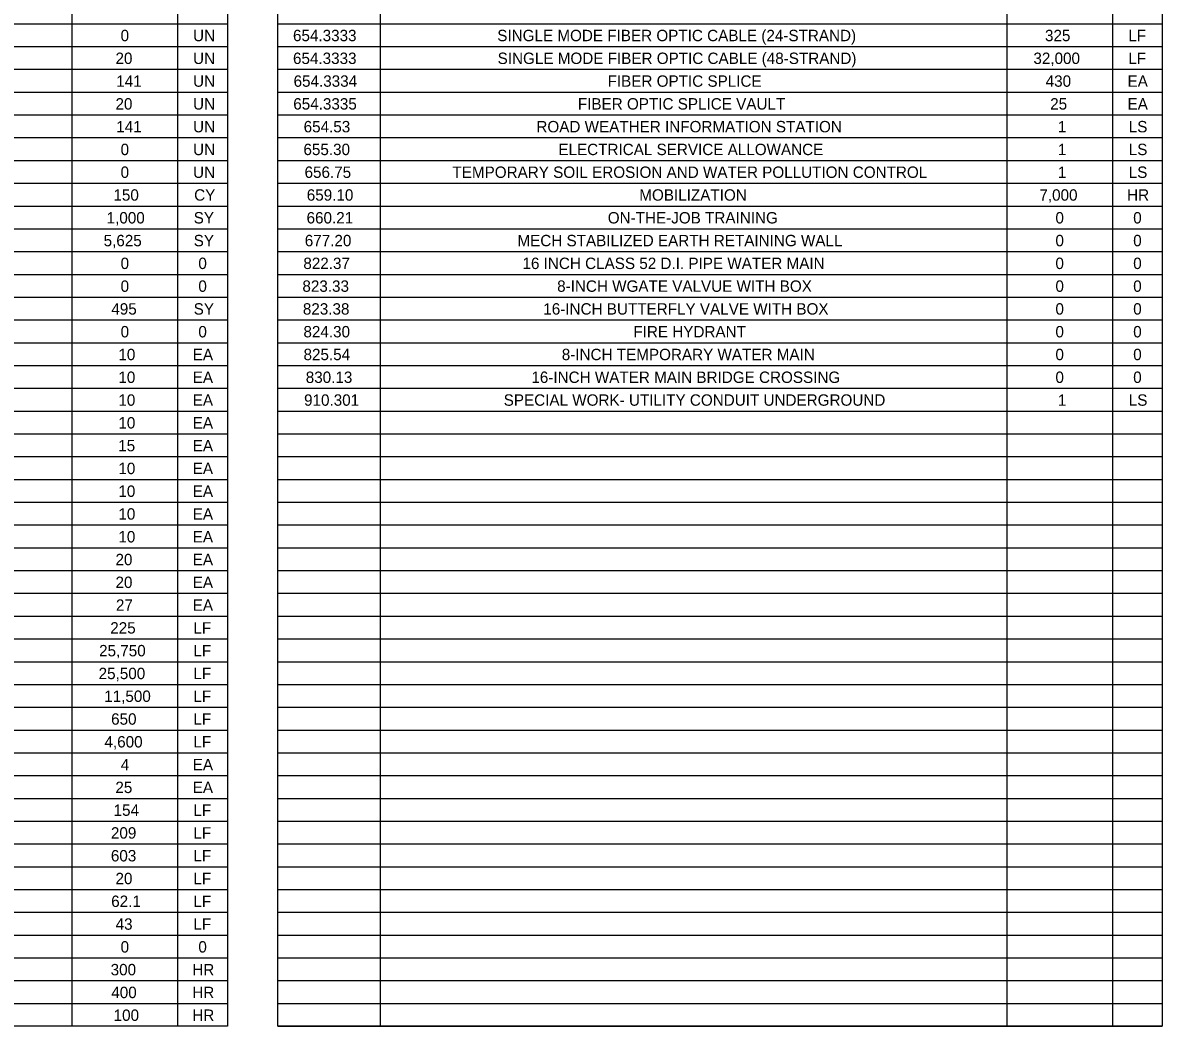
# Model space of a CAD drawing. Extents: x -18.7 to 5.6, y -2.7 to 4.
# Drawn here: x 4.632 to 5.617, y 0.019 to 0.886 of the extents above; entities that cross this region are included whole.
import ezdxf

# ---------------------------------------------------------------- set-up
doc = ezdxf.new("R2010")
doc.units = 0
doc.layers.add('ANNOTATION', color=7, linetype='Continuous')
doc.layers.add('BORDER', color=7, linetype='Continuous')

msp = doc.modelspace()

# ---------------------------------------------------------------- linework, layer by layer
at = {"layer": 'BORDER'}
for p, q in [((4.67472, 1.73155), (4.67472, 0.01886)), ((4.76611, 1.73155), (4.76611, 0.01886)), ((4.94124, 1.73155), (4.94124, 0.01886)), ((5.48258, 1.73155), (5.48258, 0.01886)), ((5.57397, 1.73155), (5.57397, 0.01886)), ((3.9448, 0.88505), (4.8091, 0.88505)), ((4.85265, 0.88505), (5.61696, 0.88505)), ((3.9448, 0.86536), (4.8091, 0.86536)), ((4.85265, 0.86536), (5.61696, 0.86536)), ((3.9448, 0.84568), (4.8091, 0.84568)), ((4.85265, 0.84568), (5.61696, 0.84568)), ((3.9448, 0.82599), (4.8091, 0.82599)), ((4.85265, 0.82599), (5.61696, 0.82599)), ((3.9448, 0.8063), (4.8091, 0.8063)), ((4.85265, 0.8063), (5.61696, 0.8063)), ((3.9448, 0.78662), (4.8091, 0.78662)), ((4.85265, 0.78662), (5.61696, 0.78662)), ((3.9448, 0.76693), (4.8091, 0.76693)), ((4.85265, 0.76693), (5.61696, 0.76693)), ((3.9448, 0.74725), (4.8091, 0.74725)), ((4.85265, 0.74725), (5.61696, 0.74725)), ((3.9448, 0.72756), (4.8091, 0.72756)), ((4.85265, 0.72756), (5.61696, 0.72756)), ((3.9448, 0.70787), (4.8091, 0.70787)), ((4.85265, 0.70787), (5.61696, 0.70787)), ((3.9448, 0.68819), (4.8091, 0.68819)), ((4.85265, 0.68819), (5.61696, 0.68819)), ((3.9448, 0.6685), (4.8091, 0.6685)), ((4.85265, 0.6685), (5.61696, 0.6685)), ((3.9448, 0.64882), (4.8091, 0.64882)), ((4.85265, 0.64882), (5.61696, 0.64882)), ((3.9448, 0.62913), (4.8091, 0.62913)), ((4.85265, 0.62913), (5.61696, 0.62913)), ((3.9448, 0.60944), (4.8091, 0.60944)), ((4.85265, 0.60944), (5.61696, 0.60944)), ((3.9448, 0.58976), (4.8091, 0.58976)), ((4.85265, 0.58976), (5.61696, 0.58976)), ((3.9448, 0.57007), (4.8091, 0.57007)), ((4.85265, 0.57007), (5.61696, 0.57007)), ((3.9448, 0.55039), (4.8091, 0.55039)), ((4.85265, 0.55039), (5.61696, 0.55039)), ((3.9448, 0.5307), (4.8091, 0.5307)), ((4.85265, 0.5307), (5.61696, 0.5307)), ((3.9448, 0.51101), (4.8091, 0.51101)), ((4.85265, 0.51101), (5.61696, 0.51101)), ((3.9448, 0.49133), (4.8091, 0.49133)), ((4.85265, 0.49133), (5.61696, 0.49133)), ((3.9448, 0.47164), (4.8091, 0.47164)), ((4.85265, 0.47164), (5.61696, 0.47164)), ((3.97991, 0.45196), (4.8091, 0.45196)), ((4.85265, 0.45196), (5.61696, 0.45196)), ((3.9448, 0.43227), (4.8091, 0.43227)), ((4.85265, 0.43227), (5.61696, 0.43227)), ((3.9448, 0.41258), (4.8091, 0.41258)), ((4.85265, 0.41258), (5.61696, 0.41258)), ((3.9448, 0.3929), (4.8091, 0.3929)), ((4.85265, 0.3929), (5.61696, 0.3929)), ((3.9448, 0.37321), (4.8091, 0.37321)), ((4.85265, 0.37321), (5.61696, 0.37321)), ((3.9448, 0.35353), (4.8091, 0.35353)), ((4.85265, 0.35353), (5.61696, 0.35353)), ((3.9448, 0.33384), (4.8091, 0.33384)), ((4.85265, 0.33384), (5.61696, 0.33384)), ((3.9448, 0.31415), (4.8091, 0.31415)), ((4.85265, 0.31415), (5.61696, 0.31415)), ((3.9448, 0.29447), (4.8091, 0.29447)), ((4.85265, 0.29447), (5.61696, 0.29447)), ((3.9448, 0.27478), (4.8091, 0.27478)), ((4.85265, 0.27478), (5.61696, 0.27478)), ((3.9448, 0.2551), (4.8091, 0.2551)), ((4.85265, 0.2551), (5.61696, 0.2551)), ((3.9448, 0.23541), (4.8091, 0.23541)), ((4.85265, 0.23541), (5.61696, 0.23541)), ((3.9448, 0.21572), (4.8091, 0.21572)), ((4.85265, 0.21572), (5.61696, 0.21572)), ((3.9448, 0.19604), (4.8091, 0.19604)), ((4.85265, 0.19604), (5.61696, 0.19604)), ((3.9448, 0.17635), (4.8091, 0.17635)), ((4.85265, 0.17635), (5.61696, 0.17635)), ((3.9448, 0.15667), (4.8091, 0.15667)), ((4.85265, 0.15667), (5.61696, 0.15667)), ((3.9448, 0.13698), (4.8091, 0.13698)), ((4.85265, 0.13698), (5.61696, 0.13698)), ((3.9448, 0.11729), (4.8091, 0.11729)), ((4.85265, 0.11729), (5.61696, 0.11729)), ((3.9448, 0.09761), (4.8091, 0.09761)), ((4.85265, 0.09761), (5.61696, 0.09761)), ((3.9448, 0.07792), (4.8091, 0.07792)), ((4.85265, 0.07792), (5.61696, 0.07792)), ((3.9448, 0.05824), (4.8091, 0.05824)), ((4.85265, 0.05824), (5.61696, 0.05824)), ((3.9448, 0.03855), (4.8091, 0.03855)), ((4.85265, 0.03855), (5.61696, 0.03855)), ((4.85265, 0.01886), (5.61696, 0.01886))]:
    msp.add_line(p, q, dxfattribs=at)
for points in [[(3.9448, 1.75123), (4.8091, 1.75123), (4.8091, 0.01886), (3.9448, 0.01886)], [(4.85265, 1.75123), (5.61696, 1.75123), (5.61696, 0.01886), (4.85265, 0.01886)]]:
    msp.add_lwpolyline(points, close=True, dxfattribs=at)

# ---------------------------------------------------------------- texts
at = {"layer": 'ANNOTATION'}
for s, height, p in [('0', 0.00984, (4.71684, 0.86996)), ('UN', 0.009843, (4.77947, 0.86996)), ('654.3333', 0.009843, (4.86582, 0.86996)), ('SINGLE MODE FIBER OPTIC CABLE (24-STRAND)', 0.009843, (5.04234, 0.86996)), ('325', 0.009843, (5.51567, 0.86996)), ('LF', 0.009843, (5.58764, 0.86996)), ('20', 0.009843, (4.71242, 0.85027)), ('UN', 0.009843, (4.77947, 0.85027)), ('654.3333', 0.009843, (4.86582, 0.85027)), ('SINGLE MODE FIBER OPTIC CABLE (48-STRAND)', 0.009843, (5.04265, 0.85027)), ('32,000', 0.009843, (5.50564, 0.85027)), ('LF', 0.009843, (5.58764, 0.85027)), ('141', 0.009843, (4.71312, 0.83059)), ('UN', 0.009843, (4.77947, 0.83059)), ('654.3334', 0.009843, (4.86632, 0.83059)), ('FIBER OPTIC SPLICE', 0.009843, (5.13768, 0.83059)), ('430', 0.009843, (5.51625, 0.83059)), ('EA', 0.009843, (5.58701, 0.83059)), ('20', 0.009843, (4.71242, 0.8109)), ('UN', 0.009843, (4.77947, 0.8109)), ('654.3335', 0.009843, (4.86605, 0.8109)), ('FIBER OPTIC SPLICE VAULT', 0.009843, (5.11199, 0.8109)), ('25', 0.009843, (5.52016, 0.8109)), ('EA', 0.009843, (5.58701, 0.8109)), ('141', 0.009843, (4.71312, 0.79121)), ('UN', 0.009843, (4.77947, 0.79121)), ('654.53', 0.009843, (4.87503, 0.79121)), ('ROAD WEATHER INFORMATION STATION', 0.009843, (5.07615, 0.79121)), ('1', 0.00984, (5.52687, 0.79121)), ('LS', 0.009843, (5.58806, 0.79121)), ('0', 0.00984, (4.71684, 0.77153)), ('UN', 0.009843, (4.77947, 0.77153)), ('655.30', 0.009843, (4.87484, 0.77153)), ('ELECTRICAL SERVICE ALLOWANCE', 0.009843, (5.09515, 0.77153)), ('1', 0.00984, (5.52687, 0.77153)), ('LS', 0.009843, (5.58806, 0.77153)), ('0', 0.00984, (4.71684, 0.75184)), ('UN', 0.009843, (4.77947, 0.75184)), ('656.75', 0.009843, (4.87581, 0.75184)), ('TEMPORARY SOIL EROSION AND WATER POLLUTION CONTROL', 0.009843, (5.00361, 0.75184)), ('1', 0.00984, (5.52687, 0.75184)), ('LS', 0.009843, (5.58806, 0.75184)), ('150', 0.009843, (4.71064, 0.73216)), ('CY', 0.009843, (4.7804, 0.73216)), ('659.10', 0.009843, (4.87771, 0.73216)), ('MOBILIZATION', 0.009843, (5.16508, 0.73216)), ('7,000', 0.009843, (5.51083, 0.73216)), ('HR', 0.009843, (5.58665, 0.73216)), ('1,000', 0.009843, (4.70476, 0.71247)), ('SY', 0.009843, (4.78001, 0.71247)), ('660.21', 0.009843, (4.87755, 0.71247)), ('ON-THE-JOB TRAINING', 0.009843, (5.13783, 0.71247)), ('0', 0.00984, (5.5247, 0.71247)), ('0', 0.00984, (5.5919, 0.71247)), ('5,625', 0.009843, (4.70216, 0.69278)), ('SY', 0.009843, (4.78001, 0.69278)), ('677.20', 0.009843, (4.876, 0.69278)), ('MECH STABILIZED EARTH RETAINING WALL', 0.009843, (5.05978, 0.69278)), ('0', 0.00984, (5.5247, 0.69278)), ('0', 0.00984, (5.5919, 0.69278)), ('0', 0.00984, (4.71684, 0.6731)), ('0', 0.00984, (4.78404, 0.6731)), ('822.37', 0.009843, (4.87476, 0.6731)), ('16 INCH CLASS 52 D.I. PIPE WATER MAIN', 0.009843, (5.06412, 0.6731)), ('0', 0.00984, (5.5247, 0.6731)), ('0', 0.00984, (5.5919, 0.6731)), ('0', 0.00984, (4.71684, 0.65341)), ('0', 0.00984, (4.78404, 0.65341)), ('823.33', 0.009843, (4.87395, 0.65341)), ('8-INCH WGATE VALVUE WITH BOX', 0.009843, (5.09409, 0.65341)), ('0', 0.00984, (5.5247, 0.65341)), ('0', 0.00984, (5.5919, 0.65341)), ('495', 0.009843, (4.70882, 0.63373)), ('SY', 0.009843, (4.78001, 0.63373)), ('823.38', 0.009843, (4.87434, 0.63373)), ('16-INCH BUTTERFLY VALVE WITH BOX', 0.009843, (5.08213, 0.63373)), ('0', 0.00984, (5.5247, 0.63373)), ('0', 0.00984, (5.5919, 0.63373)), ('0', 0.00984, (4.71684, 0.61404)), ('0', 0.00984, (4.78404, 0.61404)), ('824.30', 0.009843, (4.87484, 0.61404)), ('FIRE HYDRANT', 0.009843, (5.15994, 0.61404)), ('0', 0.00984, (5.5247, 0.61404)), ('0', 0.00984, (5.5919, 0.61404)), ('10', 0.009843, (4.7149, 0.59435)), ('EA', 0.009843, (4.77916, 0.59435)), ('825.54', 0.009843, (4.87492, 0.59435)), ('8-INCH TEMPORARY WATER MAIN', 0.009843, (5.09809, 0.59435)), ('0', 0.00984, (5.5247, 0.59435)), ('0', 0.00984, (5.5919, 0.59435)), ('10', 0.009843, (4.7149, 0.57467)), ('EA', 0.009843, (4.77916, 0.57467)), ('830.13', 0.009843, (4.87682, 0.57467)), ('16-INCH WATER MAIN BRIDGE CROSSING', 0.009843, (5.07181, 0.57467)), ('0', 0.00984, (5.5247, 0.57467)), ('0', 0.00984, (5.5919, 0.57467)), ('10', 0.009843, (4.7149, 0.55498)), ('EA', 0.009843, (4.77916, 0.55498)), ('910.301', 0.009843, (4.87539, 0.55498)), ('SPECIAL WORK- UTILITY CONDUIT UNDERGROUND', 0.009843, (5.04789, 0.55498)), ('1', 0.00984, (5.52687, 0.55498)), ('LS', 0.009843, (5.58806, 0.55498)), ('10', 0.009843, (4.7149, 0.5353)), ('EA', 0.009843, (4.77916, 0.5353)), ('15', 0.009843, (4.71479, 0.51561)), ('EA', 0.009843, (4.77916, 0.51561)), ('10', 0.009843, (4.7149, 0.49592)), ('EA', 0.009843, (4.77916, 0.49592)), ('10', 0.009843, (4.7149, 0.47624)), ('EA', 0.009843, (4.77916, 0.47624)), ('10', 0.009843, (4.7149, 0.45655)), ('EA', 0.009843, (4.77916, 0.45655)), ('10', 0.009843, (4.7149, 0.43687)), ('EA', 0.009843, (4.77916, 0.43687)), ('20', 0.009843, (4.71242, 0.41718)), ('EA', 0.009843, (4.77916, 0.41718)), ('20', 0.009843, (4.71242, 0.39749)), ('EA', 0.009843, (4.77916, 0.39749)), ('27', 0.009843, (4.71281, 0.37781)), ('EA', 0.009843, (4.77916, 0.37781)), ('225', 0.009843, (4.70789, 0.35812)), ('LF', 0.009843, (4.77978, 0.35812)), ('25,750', 0.009843, (4.69825, 0.33844)), ('LF', 0.009843, (4.77978, 0.33844)), ('25,500', 0.009843, (4.69786, 0.31875)), ('LF', 0.009843, (4.77978, 0.31875)), ('11,500', 0.009843, (4.70267, 0.29906)), ('LF', 0.009843, (4.77978, 0.29906)), ('650', 0.009843, (4.70863, 0.27938)), ('LF', 0.009843, (4.77978, 0.27938)), ('4,600', 0.009843, (4.7029, 0.25969)), ('LF', 0.009843, (4.77978, 0.25969)), ('4', 0.00984, (4.71699, 0.24001)), ('EA', 0.009843, (4.77916, 0.24001)), ('25', 0.009843, (4.71231, 0.22032)), ('EA', 0.009843, (4.77916, 0.22032)), ('154', 0.009843, (4.7108, 0.20063)), ('LF', 0.009843, (4.77978, 0.20063)), ('209', 0.009843, (4.70847, 0.18095)), ('LF', 0.009843, (4.77978, 0.18095)), ('603', 0.009843, (4.70843, 0.16126)), ('LF', 0.009843, (4.77978, 0.16126)), ('20', 0.009843, (4.71242, 0.14158)), ('LF', 0.009843, (4.77978, 0.14158)), ('62.1', 0.009843, (4.70871, 0.12189)), ('LF', 0.009843, (4.77978, 0.12189)), ('43', 0.009843, (4.71254, 0.1022)), ('LF', 0.009843, (4.77978, 0.1022)), ('0', 0.00984, (4.71684, 0.08252)), ('0', 0.00984, (4.78404, 0.08252)), ('300', 0.009843, (4.70824, 0.06283)), ('HR', 0.009843, (4.77879, 0.06283)), ('400', 0.009843, (4.70878, 0.04315)), ('HR', 0.009843, (4.77879, 0.04315)), ('100', 0.009843, (4.7108, 0.02346)), ('HR', 0.009843, (4.77879, 0.02346))]:
    msp.add_text(s, height=height, dxfattribs=at).set_placement(p)

doc.saveas('drawing.dxf')
